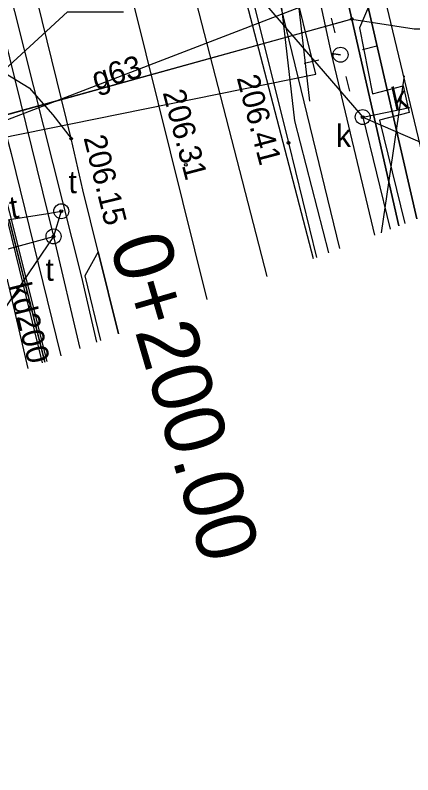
# Model space of a CAD drawing. Extents: x 6512606 to 6513006, y 6022524 to 6022728.
# Drawn here: x 6512859.05 to 6512872.32, y 6022553.23 to 6022578.56 of the extents above; entities that cross this region are included whole.
import ezdxf

# ---------------------------------------------------------------- set-up
doc = ezdxf.new("R2010")
doc.units = 0
for name, color, linetype in [('217-kontur klasyfikacyjny', 7, 'Continuous'), ('218-kontur użytku gruntowego', 7, 'Continuous'), ('219-działka ewidencyjna', 7, 'Continuous'), ('312-budynek ewidencyjny', 7, 'Continuous'), ('4', 7, 'Continuous'), ('chodnik (powierzchnia)', 7, 'Continuous'), ('Default', 7, 'Continuous'), ('inna obudowa przewodu - sieć gazowa (linia)', 7, 'Continuous'), ('jezdnia (powierzchnia)', 7, 'Continuous'), ('krawężnik (linia)', 7, 'Continuous'), ('latarnia na słupie lub maszcie (punkt)', 7, 'Continuous'), ('Obszar opracowania', 7, 'Continuous'), ('plac (powierzchnia)', 7, 'Continuous'), ('przewód elektroenergetyczny (linia)', 7, 'Continuous'), ('przewód elektroenergetyczny (linia)-Atr1', 7, 'Continuous'), ('przewód gazowy (linia)', 7, 'Continuous'), ('przewód gazowy (linia)-Atr1', 7, 'Continuous'), ('przewód kanalizacyjny (linia)', 7, 'Continuous'), ('przewód kanalizacyjny (linia)-Atr1', 7, 'Continuous'), ('przewód telekomunikacyjny (linia)', 7, 'Continuous'), ('przewód telekomunikacyjny (linia)-Atr1', 7, 'Continuous'), ('przewód wodociągowy (linia)', 7, 'Continuous'), ('psr_os', 7, 'Continuous'), ('punkt o określonej wysokości (sieć gazowa)', 7, 'Continuous'), ('punkt o określonej wysokości (sieć gazowa)-Atr2', 7, 'Continuous'), ('punkt o określonej wysokości (sieć kanalizacyjna)', 7, 'Continuous'), ('punkt o określonej wysokości (sieć kanalizacyjna)-Atr2', 7, 'Continuous'), ('punkt o określonej wysokości (sieć telekomunikacyjna)', 7, 'Continuous'), ('punkt o określonej wysokości (sieć telekomunikacyjna)-Atr2', 7, 'Continuous'), ('punkt wysokościowy sztuczny', 7, 'Continuous'), ('punkt wysokościowy sztuczny-Atr2', 7, 'Continuous'), ('rura ochronna - przewód gazowy (linia)', 7, 'Continuous'), ('słup (punkt)', 7, 'Continuous'), ('właz okrągły - siec kanalizacyjna (punkt)', 7, 'Continuous'), ('właz okrągły - siec kanalizacyjna (punkt)-Atr17', 7, 'Continuous'), ('właz okrągły - siec telekomunikacyjna (punkt)', 7, 'Continuous'), ('właz okrągły - siec telekomunikacyjna (punkt)-Atr17', 7, 'Continuous')]:
    doc.layers.add(name, color=color, linetype=linetype)

# ---------------------------------------------------------------- blocks, each defined once
blk = doc.blocks.new('US22')
at = {"layer": 'Default'}
blk.add_circle((0, 0), 2.5, dxfattribs=at)
blk = doc.blocks.new('PW01')
at = {"layer": 'Default'}
blk.add_circle((0, 0), 0.45, dxfattribs=at)
blk = doc.blocks.new('PW02')
at = {"layer": 'Default'}
blk.add_circle((0, 0), 0.45, dxfattribs=at)
blk = doc.blocks.new('SM011')
at = {"layer": 'Default'}
for p, q in [((-5.3, 5.31), (-8.83, 8.84)), ((5.31, 5.31), (8.84, 8.84)), ((-5.3, -5.3), (-8.83, -8.83)), ((5.31, -5.3), (8.84, -8.83))]:
    blk.add_line(p, q, dxfattribs=at)
blk = doc.blocks.new('SM04')
at = {"layer": 'Default'}
blk.add_circle((0, 0), 2.5, dxfattribs=at)

msp = doc.modelspace()

# ---------------------------------------------------------------- linework, layer by layer
at = {"layer": '217-kontur klasyfikacyjny'}
msp.add_lwpolyline([(6512869.68, 6022583.86), (6512872.457, 6022571.764)], dxfattribs=at)
at = {"layer": '218-kontur użytku gruntowego'}
for points in [[(6512869.68, 6022583.86), (6512872.457, 6022571.764)], [(6512872.457, 6022571.764), (6512869.68, 6022583.86)], [(6512860.035, 6022566.988), (6512858.85, 6022571.74)], [(6512858.85, 6022571.74), (6512860.035, 6022566.988)]]:
    msp.add_lwpolyline(points, dxfattribs=at)
at = {"layer": '219-działka ewidencyjna'}
for points in [[(6512872.457, 6022571.764), (6512869.68, 6022583.86)], [(6512858.85, 6022571.74), (6512860.035, 6022566.988)]]:
    msp.add_lwpolyline(points, dxfattribs=at)
at = {"layer": '312-budynek ewidencyjny'}
msp.add_lwpolyline([(6512873.106, 6022572.014), (6512871.27, 6022579.67)], dxfattribs=at)
at = {"layer": '4'}
for points in [[(6512872.457, 6022571.764), (6512869.68, 6022583.86)], [(6512858.85, 6022571.74), (6512860.035, 6022566.988)]]:
    msp.add_lwpolyline(points, dxfattribs=at)
at = {"layer": 'chodnik (powierzchnia)'}
for points in [[(6512859.96, 6022566.959), (6512857.52, 6022576.87)], [(6512861.82, 6022570.67), (6512861.37, 6022569.87), (6512861.903, 6022567.706)]]:
    msp.add_lwpolyline(points, dxfattribs=at)
at = {"layer": 'inna obudowa przewodu - sieć gazowa (linia)'}
msp.add_lwpolyline([(6512868.52, 6022585.4), (6512869.58, 6022581.52), (6512870.29, 6022578.43), (6512871.862, 6022571.535)], dxfattribs=at)
at = {"layer": 'jezdnia (powierzchnia)'}
msp.add_lwpolyline([(6512858.01, 6022586.22), (6512857.96, 6022585.04), (6512857.46, 6022583.85), (6512856.78, 6022583.14), (6512856.25, 6022582.7), (6512855.73, 6022582.41), (6512857.16, 6022576.8), (6512857.52, 6022576.87), (6512858.5, 6022576.75), (6512859.52, 6022576.13), (6512860.31, 6022575.24), (6512860.92, 6022574.44)], close=True, dxfattribs=at)
msp.add_lwpolyline([(6512861.82, 6022570.67), (6512862.495, 6022567.933)], dxfattribs=at)
at = {"layer": 'krawężnik (linia)'}
for points in [[(6512862.85, 6022595.89), (6512865.97, 6022583.13), (6512868.17, 6022574.3)], [(6512862.495, 6022567.933), (6512861.82, 6022570.67), (6512861.31, 6022572.73), (6512860.92, 6022574.44)], [(6512868.17, 6022574.3), (6512869.105, 6022570.475)]]:
    msp.add_lwpolyline(points, dxfattribs=at)
at = {"layer": 'Obszar opracowania'}
msp.add_lwpolyline([(6512710.98, 6022693.84), (6512748.35, 6022694.16), (6512798.11, 6022695.25), (6512807.47, 6022695.46), (6512809.66, 6022606.87), (6512863.71, 6022622.03), (6512875.13, 6022581.36), (6512755.22, 6022535.25), (6512691.61, 6022568.03), (6512709.16, 6022605.16)], close=True, dxfattribs=at)
at = {"layer": 'plac (powierzchnia)'}
msp.add_lwpolyline([(6512868.97, 6022586.93), (6512869.83, 6022584.57), (6512871.07, 6022579.37), (6512870.54, 6022578.14), (6512870.98, 6022575.93), (6512872, 6022576.2), (6512872.2, 6022575.31), (6512871.21, 6022575.06), (6512872.057, 6022571.61)], dxfattribs=at)
at = {"layer": 'przewód elektroenergetyczny (linia)'}
for points in [[(6512802.27, 6022673.66), (6512807.42, 6022670.09), (6512811.38, 6022666.87), (6512814.66, 6022663.43), (6512826.4, 6022651.65), (6512827.82, 6022650.09), (6512834.03, 6022642.46), (6512842.84, 6022631.19), (6512844.67, 6022626.95), (6512847.57, 6022619.87), (6512849.81, 6022612.67), (6512853.56, 6022600.08), (6512856.46, 6022588.83), (6512861.26, 6022569.82), (6512861.768, 6022567.654)], [(6512861.56, 6022603.29), (6512861.94, 6022603.39), (6512866.18, 6022583.61), (6512856.81, 6022581.85), (6512858.91, 6022573.95), (6512860.571, 6022567.194)], [(6512869.91, 6022577.24), (6512869.61, 6022577.28), (6512867.83, 6022585.48), (6512865.69, 6022591.55), (6512863.34, 6022601.78), (6512862.79, 6022603.03), (6512861.56, 6022603.29)], [(6512852.76, 6022570.72), (6512852.4, 6022572.17), (6512858.48, 6022574.45), (6512869.09, 6022576.59), (6512867.69, 6022582.27), (6512881.15, 6022586.16), (6512880.7, 6022587.82)], [(6512881.03, 6022586.32), (6512872.09, 6022583.77), (6512862.68, 6022581.17), (6512856.97, 6022579.46), (6512860.103, 6022567.013)], [(6512866.18, 6022583.61), (6512856.81, 6022581.85), (6512858.91, 6022573.95), (6512860.571, 6022567.194)], [(6512867.5, 6022582.68), (6512868.37, 6022575.03), (6512869.514, 6022570.632)], [(6512871.057, 6022571.226), (6512869.61, 6022577.28), (6512869.91, 6022577.24)]]:
    msp.add_lwpolyline(points, dxfattribs=at)
at = {"layer": 'przewód elektroenergetyczny (linia)-Atr1'}
msp.add_lwpolyline([(6512857.85, 6022575.97), (6512860.8, 6022578.67), (6512862.661, 6022578.67)], dxfattribs=at)
at = {"layer": 'przewód gazowy (linia)'}
for points in [[(6512871.862, 6022571.535), (6512870.29, 6022578.43), (6512869.58, 6022581.52), (6512865.64, 6022595.96), (6512860.06, 6022617.51), (6512858.39, 6022625.33), (6512855.49, 6022634.19), (6512854.83, 6022641.62)], [(6512870.29, 6022578.43), (6512856.86, 6022574.7), (6512856.85, 6022574.71)]]:
    msp.add_lwpolyline(points, dxfattribs=at)
at = {"layer": 'przewód kanalizacyjny (linia)'}
for points in [[(6512860.63, 6022596.28), (6512867.451, 6022569.839)], [(6512861.16, 6022586.16), (6512870.65, 6022575.16)], [(6512865.461, 6022569.074), (6512862.2, 6022582.21), (6512861.16, 6022586.16)], [(6512868.19, 6022581.69), (6512868.88, 6022575.69)], [(6512872.03, 6022576.53), (6512871.262, 6022571.304)], [(6512870.65, 6022575.16), (6512872.22, 6022575.48)], [(6512870.65, 6022575.16), (6512871.573, 6022571.424)], [(6512857.81, 6022573.85), (6512859.474, 6022566.772)]]:
    msp.add_lwpolyline(points, dxfattribs=at)
at = {"layer": 'przewód telekomunikacyjny (linia)'}
for points in [[(6512836.6, 6022638.32), (6512844.42, 6022625.21), (6512848.91, 6022613.6), (6512851.86, 6022605.02), (6512853.91, 6022597.19), (6512860.14, 6022571.94), (6512860.33, 6022571.18)], [(6512857.7, 6022571.57), (6512860.14, 6022571.94), (6512860.59, 6022572.02)], [(6512860.59, 6022572.02), (6512860.33, 6022571.18)], [(6512857.95, 6022570.53), (6512860.33, 6022571.18)], [(6512860.33, 6022571.18), (6512861.213, 6022567.441)]]:
    msp.add_lwpolyline(points, dxfattribs=at)
at = {"layer": 'przewód wodociągowy (linia)'}
for points in [[(6512869.887, 6022570.776), (6512864.23, 6022594.01), (6512863.79, 6022596.02), (6512861.84, 6022602.88)], [(6512869.005, 6022570.437), (6512862.93, 6022593.72)]]:
    msp.add_lwpolyline(points, dxfattribs=at)
at = {"layer": 'punkt o określonej wysokości (sieć gazowa)-Atr2'}
msp.add_lwpolyline([(6512870.29, 6022578.43), (6512872.37, 6022578.1), (6512875.537, 6022578.1)], dxfattribs=at)
at = {"layer": 'punkt o określonej wysokości (sieć kanalizacyjna)-Atr2'}
msp.add_lwpolyline([(6512870.65, 6022575.16), (6512873.07, 6022574.11), (6512876.243, 6022574.11)], dxfattribs=at)
at = {"layer": 'punkt o określonej wysokości (sieć telekomunikacyjna)-Atr2'}
msp.add_lwpolyline([(6512860.33, 6022571.18), (6512858.01, 6022567.79), (6512854.875, 6022567.79)], dxfattribs=at)
at = {"layer": 'rura ochronna - przewód gazowy (linia)'}
msp.add_lwpolyline([(6512870.05, 6022578.36), (6512856.85, 6022574.71)], dxfattribs=at)

# ---------------------------------------------------------------- block references
at = {"layer": 'latarnia na słupie lub maszcie (punkt)', "xscale": 0.10000000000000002, "yscale": 0.1, "rotation": -31.239}
msp.add_blockref('SM011', (6512869.91, 6022577.24), dxfattribs=at)
at = {"layer": 'punkt o określonej wysokości (sieć gazowa)', "xscale": 0.1, "yscale": 0.10000000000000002}
msp.add_blockref('PW01', (6512870.29, 6022578.43), dxfattribs=at)
at = {"layer": 'punkt o określonej wysokości (sieć kanalizacyjna)', "xscale": 0.1, "yscale": 0.10000000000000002}
msp.add_blockref('PW01', (6512870.65, 6022575.16), dxfattribs=at)
at = {"layer": 'punkt o określonej wysokości (sieć telekomunikacyjna)', "xscale": 0.1, "yscale": 0.10000000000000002}
for p, rotation in [((6512860.59, 6022572.02), -170.143), ((6512860.33, 6022571.18), 13.134000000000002)]:
    msp.add_blockref('PW01', p, dxfattribs=dict(at, rotation=rotation))
at = {"layer": 'punkt wysokościowy sztuczny', "xscale": 0.1, "yscale": 0.10000000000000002}
for p in [(6512860.92, 6022574.44), (6512868.17, 6022574.3), (6512864.75, 6022573.57)]:
    msp.add_blockref('PW02', p, dxfattribs=at)
at = {"layer": 'słup (punkt)', "xscale": 0.1, "yscale": 0.10000000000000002}
msp.add_blockref('SM04', (6512869.91, 6022577.24), dxfattribs=at)
at = {"layer": 'właz okrągły - siec kanalizacyjna (punkt)', "xscale": 0.1, "yscale": 0.10000000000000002}
msp.add_blockref('US22', (6512870.65, 6022575.16), dxfattribs=at)
at = {"layer": 'właz okrągły - siec telekomunikacyjna (punkt)', "xscale": 0.1, "yscale": 0.10000000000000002}
for p, rotation in [((6512860.59, 6022572.02), -170.143), ((6512860.33, 6022571.18), 13.134000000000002)]:
    msp.add_blockref('US22', p, dxfattribs=dict(at, rotation=rotation))

# ---------------------------------------------------------------- texts
at = {"layer": 'przewód gazowy (linia)-Atr1'}
msp.add_text('g63', height=0.75, rotation=16.329, dxfattribs=at).set_placement((6512861.74, 6022576.05))
at = {"layer": 'przewód kanalizacyjny (linia)-Atr1'}
for s, rotation, p in [('k', 12.567, (6512871.71, 6022575.38)), ('kd200', 284.064, (6512858.83, 6022569.54))]:
    msp.add_text(s, height=0.75, rotation=rotation, dxfattribs=at).set_placement(p)
at = {"layer": 'przewód telekomunikacyjny (linia)-Atr1'}
msp.add_text('t', height=0.75, rotation=9.694, dxfattribs=at).set_placement((6512858.93, 6022571.76))
at = {"layer": 'psr_os'}
msp.add_text('0+200.00', height=2, rotation=286.2942, dxfattribs=at).set_placement((6512862.182, 6022570.955))
at = {"layer": 'punkt wysokościowy sztuczny-Atr2'}
for s, rotation, p in [('206.41', 284.83, (6512866.44, 6022576.47)), ('206.31', 284.757, (6512863.97, 6022575.98)), ('206.15', 283.799, (6512861.33, 6022574.47))]:
    msp.add_text(s, height=0.75, rotation=rotation, dxfattribs=at).set_placement(p)
at = {"layer": 'właz okrągły - siec kanalizacyjna (punkt)-Atr17'}
msp.add_text('k', height=0.75, dxfattribs=at).set_placement((6512869.76, 6022574.16))
at = {"layer": 'właz okrągły - siec telekomunikacyjna (punkt)-Atr17'}
for p in [(6512860.83, 6022572.62), (6512860.06, 6022569.7)]:
    msp.add_text('t', height=0.75, dxfattribs=at).set_placement(p)

doc.saveas('drawing.dxf')
